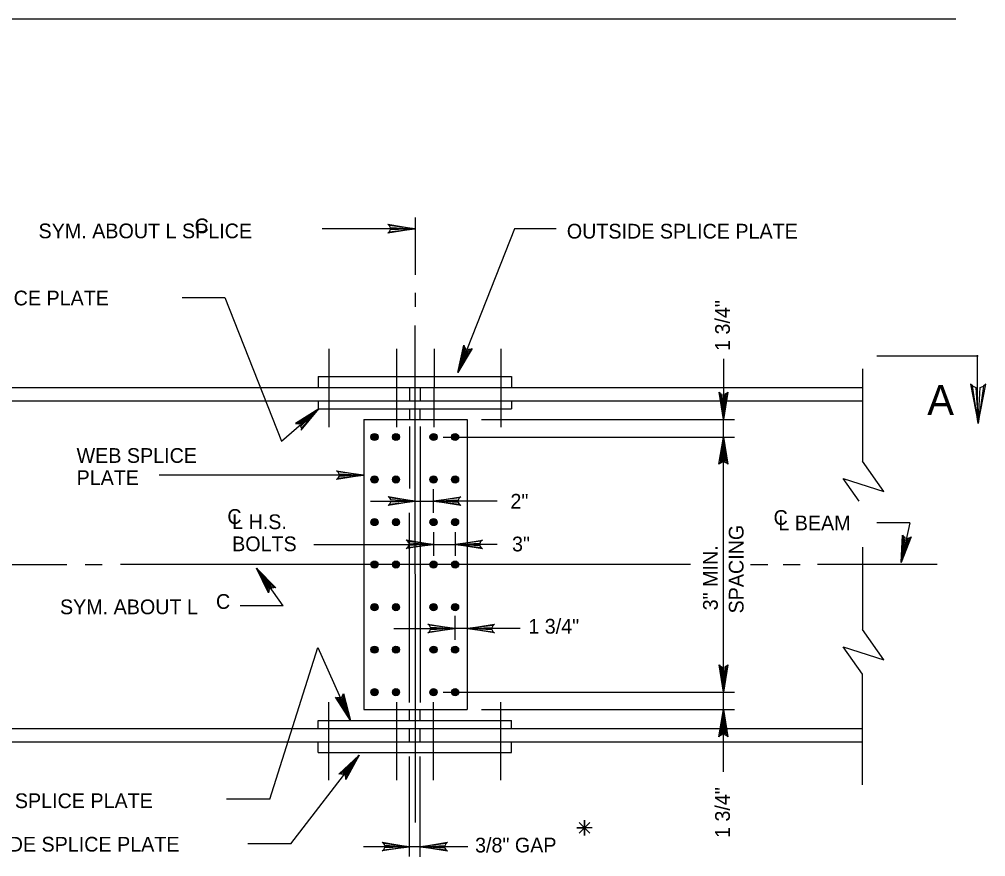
# Model space of a CAD drawing. Extents: x 638466 to 639375, y 297808 to 298996.
# Drawn here: x 638619.3 to 638831.8, y 298507.4 to 298691.6 of the extents above; entities that cross this region are included whole.
import ezdxf

# ---------------------------------------------------------------- set-up
doc = ezdxf.new("R2010")
doc.units = 0
for name, color, linetype in [('1', 7, 'Continuous'), ('2', 7, 'Continuous'), ('4', 7, 'Continuous')]:
    doc.layers.add(name, color=color, linetype=linetype)

msp = doc.modelspace()

# ---------------------------------------------------------------- linework, layer by layer
at = {"layer": '1'}
for points in [[(638700.6, 298646.27), (638700.81, 298645.85), (638706.32, 298645.55), (638700.6, 298646.27), (638700.3, 298646.52), (638706.32, 298645.55), (638700.81, 298645.28), (638700.61, 298644.86), (638706.32, 298645.55), (638700.3, 298644.59), (638700.61, 298644.86)], [(638718.49, 298619.02), (638718.03, 298618.97), (638715.72, 298613.96), (638718.49, 298619.02), (638718.83, 298619.2), (638715.72, 298613.96), (638717.49, 298619.18), (638717.18, 298619.52), (638715.72, 298613.96), (638717.04, 298619.91), (638717.18, 298619.52)], [(638828.91, 298610.97), (638829.62, 298610.66), (638830.15, 298602.73), (638828.91, 298610.97), (638828.47, 298611.39), (638830.15, 298602.73), (638830.61, 298610.65), (638831.32, 298610.95), (638830.15, 298602.73), (638831.8, 298611.39), (638831.32, 298610.95)], [(638774.83, 298609.29), (638774.42, 298609.08), (638774.11, 298603.57), (638774.83, 298609.29), (638775.08, 298609.58), (638774.11, 298603.57), (638773.84, 298609.07), (638773.43, 298609.27), (638774.11, 298603.57), (638773.16, 298609.58), (638773.43, 298609.27)], [(638681.3, 298601.65), (638681.19, 298602.1), (638685.16, 298605.93), (638681.3, 298601.65), (638681.24, 298601.27), (638685.16, 298605.93), (638680.82, 298602.54), (638680.4, 298602.72), (638685.16, 298605.93), (638679.98, 298602.73), (638680.4, 298602.72)], [(638773.4, 298594.02), (638773.81, 298594.23), (638774.11, 298599.74), (638773.4, 298594.02), (638773.14, 298593.73), (638774.11, 298599.74), (638774.38, 298594.24), (638774.8, 298594.04), (638774.11, 298599.74), (638775.07, 298593.73), (638774.8, 298594.04)], [(638689.3, 298592.05), (638689.51, 298591.64), (638695.02, 298591.33), (638689.3, 298592.05), (638689.01, 298592.3), (638695.02, 298591.33), (638689.51, 298591.06), (638689.31, 298590.65), (638695.02, 298591.33), (638689.01, 298590.38), (638689.31, 298590.65)], [(638700.66, 298586.38), (638700.87, 298585.96), (638706.38, 298585.66), (638700.66, 298586.38), (638700.37, 298586.63), (638706.38, 298585.66), (638700.88, 298585.39), (638700.68, 298584.97), (638706.38, 298585.66), (638700.37, 298584.7), (638700.68, 298584.97)], [(638716.1, 298584.94), (638715.88, 298585.35), (638710.37, 298585.66), (638716.1, 298584.94), (638716.39, 298584.69), (638710.37, 298585.66), (638715.88, 298585.93), (638716.08, 298586.34), (638710.37, 298585.66), (638716.39, 298586.61), (638716.08, 298586.34)], [(638704.65, 298576.85), (638704.87, 298576.43), (638710.37, 298576.13), (638704.65, 298576.85), (638704.36, 298577.1), (638710.37, 298576.13), (638704.87, 298575.86), (638704.67, 298575.45), (638710.37, 298576.13), (638704.36, 298575.18), (638704.67, 298575.45)], [(638720.82, 298575.41), (638720.61, 298575.82), (638715.1, 298576.13), (638720.82, 298575.41), (638721.11, 298575.16), (638715.1, 298576.13), (638720.6, 298576.4), (638720.8, 298576.81), (638715.1, 298576.13), (638721.11, 298577.08), (638720.8, 298576.81)], [(638815.1, 298577.54), (638814.65, 298577.42), (638813.19, 298572.1), (638815.1, 298577.54), (638815.41, 298577.77), (638813.19, 298572.1), (638814.09, 298577.54), (638813.73, 298577.82), (638813.19, 298572.1), (638813.53, 298578.18), (638813.73, 298577.82)], [(638674.13, 298565.82), (638674.34, 298566.24), (638671.4, 298570.91), (638674.13, 298565.82), (638674.09, 298565.44), (638671.4, 298570.91), (638674.81, 298566.58), (638675.26, 298566.65), (638671.4, 298570.91), (638675.66, 298566.55), (638675.26, 298566.65)], [(638709.38, 298558.32), (638709.59, 298557.9), (638715.1, 298557.6), (638709.38, 298558.32), (638709.09, 298558.57), (638715.1, 298557.6), (638709.59, 298557.33), (638709.39, 298556.92), (638715.1, 298557.6), (638709.09, 298556.65), (638709.39, 298556.92)], [(638723.46, 298556.88), (638723.25, 298557.29), (638717.74, 298557.6), (638723.46, 298556.88), (638723.75, 298556.63), (638717.74, 298557.6), (638723.25, 298557.87), (638723.45, 298558.28), (638717.74, 298557.6), (638723.75, 298558.55), (638723.45, 298558.28)], [(638774.83, 298549.33), (638774.42, 298549.12), (638774.11, 298543.61), (638774.83, 298549.33), (638775.08, 298549.62), (638774.11, 298543.61), (638773.84, 298549.11), (638773.43, 298549.32), (638774.11, 298543.61), (638773.16, 298549.62), (638773.43, 298549.32)], [(638690.42, 298542.94), (638690.13, 298542.58), (638692.09, 298537.42), (638690.42, 298542.94), (638690.53, 298543.31), (638692.09, 298537.42), (638689.6, 298542.34), (638689.15, 298542.36), (638692.09, 298537.42), (638688.77, 298542.53), (638689.15, 298542.36)], [(638773.4, 298534.07), (638773.81, 298534.28), (638774.11, 298539.79), (638773.4, 298534.07), (638773.14, 298533.77), (638774.11, 298539.79), (638774.38, 298534.28), (638774.8, 298534.08), (638774.11, 298539.79), (638775.07, 298533.77), (638774.8, 298534.08)], [(638689.95, 298525.68), (638690.41, 298525.6), (638694.01, 298529.78), (638689.95, 298525.68), (638689.57, 298525.6), (638694.01, 298529.78), (638690.87, 298525.25), (638691.07, 298524.84), (638694.01, 298529.78), (638691.1, 298524.43), (638691.07, 298524.84)], [(638699.34, 298510.35), (638699.55, 298509.93), (638705.06, 298509.63), (638699.34, 298510.35), (638699.04, 298510.6), (638705.06, 298509.63), (638699.55, 298509.36), (638699.35, 298508.95), (638705.06, 298509.63), (638699.04, 298508.68), (638699.35, 298508.95)], [(638713.14, 298508.91), (638712.93, 298509.33), (638707.42, 298509.63), (638713.14, 298508.91), (638713.43, 298508.66), (638707.42, 298509.63), (638712.92, 298509.9), (638713.12, 298510.31), (638707.42, 298509.63), (638713.43, 298510.59), (638713.12, 298510.31)]]:
    msp.add_lwpolyline(points, dxfattribs=at)
at = {"layer": '2'}
for p, q in [((638706.31, 298648.02), (638706.32, 298635.41)), ((638706.33, 298631.47), (638706.33, 298628.4)), ((638706.42, 298514.94), (638706.33, 298624.24)), ((638687.34, 298619.12), (638687.34, 298601.93)), ((638702.2, 298619.12), (638702.21, 298601.94)), ((638710.47, 298619.12), (638710.46, 298601.94)), ((638725.14, 298619.12), (638725.14, 298601.93)), ((638804.7, 298614.72), (638804.7, 298594.42)), ((638684.98, 298613.02), (638727.5, 298613.02)), ((638684.98, 298613.02), (638684.98, 298610.65)), ((638727.5, 298613.02), (638727.5, 298610.65)), ((638607.78, 298610.65), (638804.7, 298610.65)), ((638705.06, 298610.65), (638705.06, 298607.7)), ((638707.42, 298610.65), (638707.42, 298607.7)), ((638607.78, 298607.7), (638804.7, 298607.7)), ((638684.98, 298607.7), (638684.98, 298605.93)), ((638727.5, 298607.7), (638727.5, 298605.93)), ((638684.98, 298605.93), (638727.5, 298605.93)), ((638705.06, 298605.93), (638705.06, 298603.57)), ((638707.42, 298603.57), (638707.42, 298605.93)), ((638695.02, 298603.57), (638717.74, 298603.57)), ((638695.02, 298603.57), (638695.02, 298539.79)), ((638717.74, 298603.57), (638717.74, 298539.79)), ((638705.06, 298602.02), (638705.06, 298588.4)), ((638707.42, 298602.02), (638707.42, 298541.34)), ((638809.43, 298587.77), (638804.7, 298594.42)), ((638803.97, 298585.66), (638800.44, 298590.62)), ((638800.44, 298590.62), (638809.43, 298587.77)), ((638705.06, 298541.34), (638705.06, 298583.08)), ((638804.7, 298575.51), (638804.7, 298557.37)), ((638809.43, 298550.72), (638804.7, 298557.37)), ((638804.7, 298547.58), (638800.44, 298553.57)), ((638800.44, 298553.57), (638809.43, 298550.72)), ((638804.7, 298523.27), (638804.7, 298547.59)), ((638687.34, 298524.23), (638687.34, 298541.42)), ((638702.3, 298524.23), (638702.3, 298541.42)), ((638710.37, 298524.23), (638710.37, 298541.42)), ((638725.14, 298524.23), (638725.14, 298541.42)), ((638695.02, 298539.79), (638717.74, 298539.79)), ((638705.06, 298537.42), (638705.06, 298539.79)), ((638707.42, 298537.42), (638707.42, 298539.79)), ((638684.98, 298537.42), (638727.5, 298537.42)), ((638684.98, 298535.65), (638684.98, 298537.42)), ((638727.5, 298535.65), (638727.5, 298537.42)), ((638607.78, 298535.65), (638804.7, 298535.65)), ((638705.06, 298532.7), (638705.06, 298535.65)), ((638707.42, 298532.7), (638707.42, 298535.65)), ((638607.78, 298532.69), (638804.7, 298532.69)), ((638684.98, 298530.34), (638684.98, 298532.7)), ((638727.5, 298530.34), (638727.5, 298532.7)), ((638684.98, 298530.34), (638727.5, 298530.34))]:
    msp.add_line(p, q, dxfattribs=at)
for centre, radius in [((638697.38, 298599.74), 0.783), ((638697.38, 298599.74), 0.727), ((638697.38, 298599.74), 0.672), ((638702.11, 298599.74), 0.783), ((638702.11, 298599.74), 0.727), ((638702.11, 298599.74), 0.672), ((638710.37, 298599.74), 0.783), ((638710.37, 298599.74), 0.727), ((638710.37, 298599.74), 0.672), ((638715.1, 298599.74), 0.783), ((638715.1, 298599.74), 0.727), ((638715.1, 298599.74), 0.672), ((638697.38, 298599.74), 0.616), ((638697.38, 298599.74), 0.561), ((638697.38, 298599.74), 0.505), ((638697.38, 298599.74), 0.449), ((638697.38, 298599.74), 0.394), ((638697.38, 298599.74), 0.338), ((638697.38, 298599.74), 0.283), ((638697.38, 298599.74), 0.227), ((638697.38, 298599.74), 0.171), ((638697.38, 298599.74), 0.116), ((638697.38, 298599.74), 0.0601), ((638702.11, 298599.74), 0.616), ((638702.11, 298599.74), 0.561), ((638702.11, 298599.74), 0.505), ((638702.11, 298599.74), 0.449), ((638702.11, 298599.74), 0.394), ((638702.11, 298599.74), 0.338), ((638702.11, 298599.74), 0.283), ((638702.11, 298599.74), 0.227), ((638702.11, 298599.74), 0.171), ((638702.11, 298599.74), 0.116), ((638702.11, 298599.74), 0.0601), ((638710.37, 298599.74), 0.616), ((638710.37, 298599.74), 0.561), ((638710.37, 298599.74), 0.505), ((638710.37, 298599.74), 0.449), ((638710.37, 298599.74), 0.394), ((638710.37, 298599.74), 0.338), ((638710.37, 298599.74), 0.283), ((638710.37, 298599.74), 0.227), ((638710.37, 298599.74), 0.171), ((638710.37, 298599.74), 0.116), ((638710.37, 298599.74), 0.0601), ((638715.1, 298599.74), 0.616), ((638715.1, 298599.74), 0.561), ((638715.1, 298599.74), 0.505), ((638715.1, 298599.74), 0.449), ((638715.1, 298599.74), 0.394), ((638715.1, 298599.74), 0.338), ((638715.1, 298599.74), 0.283), ((638715.1, 298599.74), 0.227), ((638715.1, 298599.74), 0.171), ((638715.1, 298599.74), 0.116), ((638715.1, 298599.74), 0.0601), ((638697.38, 298590.39), 0.783), ((638697.38, 298590.39), 0.727), ((638697.38, 298590.39), 0.672), ((638697.38, 298590.39), 0.616), ((638697.38, 298590.39), 0.561), ((638697.38, 298590.39), 0.505), ((638697.38, 298590.39), 0.449), ((638697.38, 298590.39), 0.394), ((638697.38, 298590.39), 0.338), ((638697.38, 298590.39), 0.283), ((638697.38, 298590.39), 0.227), ((638697.38, 298590.39), 0.171), ((638697.38, 298590.39), 0.116), ((638697.38, 298590.39), 0.0601), ((638702.11, 298590.39), 0.783), ((638702.11, 298590.39), 0.727), ((638702.11, 298590.39), 0.672), ((638702.11, 298590.39), 0.616), ((638702.11, 298590.39), 0.561), ((638702.11, 298590.39), 0.505), ((638702.11, 298590.39), 0.449), ((638702.11, 298590.39), 0.394), ((638702.11, 298590.39), 0.338), ((638702.11, 298590.39), 0.283), ((638702.11, 298590.39), 0.227), ((638702.11, 298590.39), 0.171), ((638702.11, 298590.39), 0.116), ((638702.11, 298590.39), 0.0601), ((638710.37, 298590.39), 0.783), ((638710.37, 298590.39), 0.727), ((638710.37, 298590.39), 0.672), ((638710.37, 298590.39), 0.616), ((638710.37, 298590.39), 0.561), ((638710.37, 298590.39), 0.505), ((638710.37, 298590.39), 0.449), ((638710.37, 298590.39), 0.394), ((638710.37, 298590.39), 0.338), ((638710.37, 298590.39), 0.283), ((638710.37, 298590.39), 0.227), ((638710.37, 298590.39), 0.171), ((638710.37, 298590.39), 0.116), ((638710.37, 298590.39), 0.0601), ((638715.1, 298590.39), 0.783), ((638715.1, 298590.39), 0.727), ((638715.1, 298590.39), 0.672), ((638715.1, 298590.39), 0.616), ((638715.1, 298590.39), 0.561), ((638715.1, 298590.39), 0.505), ((638715.1, 298590.39), 0.449), ((638715.1, 298590.39), 0.394), ((638715.1, 298590.39), 0.338), ((638715.1, 298590.39), 0.283), ((638715.1, 298590.39), 0.227), ((638715.1, 298590.39), 0.171), ((638715.1, 298590.39), 0.116), ((638715.1, 298590.39), 0.0601), ((638697.38, 298581.03), 0.783), ((638697.38, 298581.03), 0.727), ((638697.38, 298581.03), 0.672), ((638697.38, 298581.03), 0.616), ((638697.38, 298581.03), 0.561), ((638697.38, 298581.03), 0.505), ((638697.38, 298581.03), 0.449), ((638697.38, 298581.03), 0.394), ((638697.38, 298581.03), 0.338), ((638697.38, 298581.03), 0.283), ((638697.38, 298581.03), 0.227), ((638702.11, 298581.03), 0.783), ((638702.11, 298581.03), 0.727), ((638702.11, 298581.03), 0.672), ((638702.11, 298581.03), 0.616), ((638702.11, 298581.03), 0.561), ((638702.11, 298581.03), 0.505), ((638702.11, 298581.03), 0.449), ((638702.11, 298581.03), 0.394), ((638702.11, 298581.03), 0.338), ((638702.11, 298581.03), 0.283), ((638702.11, 298581.03), 0.227), ((638710.37, 298581.03), 0.783), ((638710.37, 298581.03), 0.727), ((638710.37, 298581.03), 0.672), ((638710.37, 298581.03), 0.616), ((638710.37, 298581.03), 0.561), ((638710.37, 298581.03), 0.505), ((638710.37, 298581.03), 0.449), ((638710.37, 298581.03), 0.394), ((638710.37, 298581.03), 0.338), ((638710.37, 298581.03), 0.283), ((638710.37, 298581.03), 0.227), ((638715.1, 298581.03), 0.783), ((638715.1, 298581.03), 0.727), ((638715.1, 298581.03), 0.672), ((638715.1, 298581.03), 0.616), ((638715.1, 298581.03), 0.561), ((638715.1, 298581.03), 0.505), ((638715.1, 298581.03), 0.449), ((638715.1, 298581.03), 0.394), ((638715.1, 298581.03), 0.338), ((638715.1, 298581.03), 0.283), ((638715.1, 298581.03), 0.227), ((638697.38, 298581.03), 0.171), ((638697.38, 298581.03), 0.116), ((638697.38, 298581.03), 0.0601), ((638702.11, 298581.03), 0.171), ((638702.11, 298581.03), 0.116), ((638702.11, 298581.03), 0.0601), ((638710.37, 298581.03), 0.171), ((638710.37, 298581.03), 0.116), ((638710.37, 298581.03), 0.0601), ((638715.1, 298581.03), 0.171), ((638715.1, 298581.03), 0.116), ((638715.1, 298581.03), 0.0601), ((638697.38, 298571.68), 0.783), ((638697.38, 298571.68), 0.727), ((638697.38, 298571.68), 0.672), ((638697.38, 298571.68), 0.616), ((638697.38, 298571.68), 0.561), ((638697.38, 298571.68), 0.505), ((638697.38, 298571.68), 0.449), ((638697.38, 298571.68), 0.394), ((638697.38, 298571.68), 0.338), ((638697.38, 298571.68), 0.283), ((638697.38, 298571.68), 0.227), ((638697.38, 298571.68), 0.171), ((638697.38, 298571.68), 0.116), ((638697.38, 298571.68), 0.0601), ((638702.11, 298571.68), 0.783), ((638702.11, 298571.68), 0.727), ((638702.11, 298571.68), 0.672), ((638702.11, 298571.68), 0.616), ((638702.11, 298571.68), 0.561), ((638702.11, 298571.68), 0.505), ((638702.11, 298571.68), 0.449), ((638702.11, 298571.68), 0.394), ((638702.11, 298571.68), 0.338), ((638702.11, 298571.68), 0.283), ((638702.11, 298571.68), 0.227), ((638702.11, 298571.68), 0.171), ((638702.11, 298571.68), 0.116), ((638702.11, 298571.68), 0.0601), ((638710.37, 298571.68), 0.783), ((638710.37, 298571.68), 0.727), ((638710.37, 298571.68), 0.672), ((638710.37, 298571.68), 0.616), ((638710.37, 298571.68), 0.561), ((638710.37, 298571.68), 0.505), ((638710.37, 298571.68), 0.449), ((638710.37, 298571.68), 0.394), ((638710.37, 298571.68), 0.338), ((638710.37, 298571.68), 0.283), ((638710.37, 298571.68), 0.227), ((638710.37, 298571.68), 0.171), ((638710.37, 298571.68), 0.116), ((638710.37, 298571.68), 0.0601), ((638715.1, 298571.68), 0.783), ((638715.1, 298571.68), 0.727), ((638715.1, 298571.68), 0.672), ((638715.1, 298571.68), 0.616), ((638715.1, 298571.68), 0.561), ((638715.1, 298571.68), 0.505), ((638715.1, 298571.68), 0.449), ((638715.1, 298571.68), 0.394), ((638715.1, 298571.68), 0.338), ((638715.1, 298571.68), 0.283), ((638715.1, 298571.68), 0.227), ((638715.1, 298571.68), 0.171), ((638715.1, 298571.68), 0.116), ((638715.1, 298571.68), 0.0601), ((638697.38, 298562.32), 0.783), ((638697.38, 298562.32), 0.727), ((638697.38, 298562.32), 0.672), ((638697.38, 298562.32), 0.616), ((638697.38, 298562.32), 0.561), ((638697.38, 298562.32), 0.505), ((638697.38, 298562.32), 0.449), ((638697.38, 298562.32), 0.394), ((638697.38, 298562.32), 0.338), ((638697.38, 298562.32), 0.283), ((638697.38, 298562.32), 0.227), ((638697.38, 298562.32), 0.171), ((638697.38, 298562.32), 0.116), ((638697.38, 298562.32), 0.0601), ((638702.11, 298562.32), 0.783), ((638702.11, 298562.32), 0.727), ((638702.11, 298562.32), 0.672), ((638702.11, 298562.32), 0.616), ((638702.11, 298562.32), 0.561), ((638702.11, 298562.32), 0.505), ((638702.11, 298562.32), 0.449), ((638702.11, 298562.32), 0.394), ((638702.11, 298562.32), 0.338), ((638702.11, 298562.32), 0.283), ((638702.11, 298562.32), 0.227), ((638702.11, 298562.32), 0.171), ((638702.11, 298562.32), 0.116), ((638702.11, 298562.32), 0.0601), ((638710.37, 298562.32), 0.783), ((638710.37, 298562.32), 0.727), ((638710.37, 298562.32), 0.672), ((638710.37, 298562.32), 0.616), ((638710.37, 298562.32), 0.561), ((638710.37, 298562.32), 0.505), ((638710.37, 298562.32), 0.449), ((638710.37, 298562.32), 0.394), ((638710.37, 298562.32), 0.338), ((638710.37, 298562.32), 0.283), ((638710.37, 298562.32), 0.227), ((638710.37, 298562.32), 0.171), ((638710.37, 298562.32), 0.116), ((638710.37, 298562.32), 0.0601), ((638715.1, 298562.32), 0.783), ((638715.1, 298562.32), 0.727), ((638715.1, 298562.32), 0.672), ((638715.1, 298562.32), 0.616), ((638715.1, 298562.32), 0.561), ((638715.1, 298562.32), 0.505), ((638715.1, 298562.32), 0.449), ((638715.1, 298562.32), 0.394), ((638715.1, 298562.32), 0.338), ((638715.1, 298562.32), 0.283), ((638715.1, 298562.32), 0.227), ((638715.1, 298562.32), 0.171), ((638715.1, 298562.32), 0.116), ((638715.1, 298562.32), 0.0601), ((638697.38, 298552.97), 0.783), ((638697.38, 298552.97), 0.727), ((638697.38, 298552.97), 0.672), ((638702.11, 298552.97), 0.783), ((638702.11, 298552.97), 0.727), ((638702.11, 298552.97), 0.672), ((638710.37, 298552.97), 0.783), ((638710.37, 298552.97), 0.727), ((638710.37, 298552.97), 0.672), ((638715.1, 298552.97), 0.783), ((638715.1, 298552.97), 0.727), ((638715.1, 298552.97), 0.672), ((638697.38, 298552.97), 0.616), ((638697.38, 298552.97), 0.561), ((638697.38, 298552.97), 0.505), ((638697.38, 298552.97), 0.449), ((638697.38, 298552.97), 0.394), ((638697.38, 298552.97), 0.338), ((638697.38, 298552.97), 0.283), ((638697.38, 298552.97), 0.227), ((638697.38, 298552.97), 0.171), ((638697.38, 298552.97), 0.116), ((638697.38, 298552.97), 0.0601), ((638702.11, 298552.97), 0.616), ((638702.11, 298552.97), 0.561), ((638702.11, 298552.97), 0.505), ((638702.11, 298552.97), 0.449), ((638702.11, 298552.97), 0.394), ((638702.11, 298552.97), 0.338), ((638702.11, 298552.97), 0.283), ((638702.11, 298552.97), 0.227), ((638702.11, 298552.97), 0.171), ((638702.11, 298552.97), 0.116), ((638702.11, 298552.97), 0.0601), ((638710.37, 298552.97), 0.616), ((638710.37, 298552.97), 0.561), ((638710.37, 298552.97), 0.505), ((638710.37, 298552.97), 0.449), ((638710.37, 298552.97), 0.394), ((638710.37, 298552.97), 0.338), ((638710.37, 298552.97), 0.283), ((638710.37, 298552.97), 0.227), ((638710.37, 298552.97), 0.171), ((638710.37, 298552.97), 0.116), ((638710.37, 298552.97), 0.0601), ((638715.1, 298552.97), 0.616), ((638715.1, 298552.97), 0.561), ((638715.1, 298552.97), 0.505), ((638715.1, 298552.97), 0.449), ((638715.1, 298552.97), 0.394), ((638715.1, 298552.97), 0.338), ((638715.1, 298552.97), 0.283), ((638715.1, 298552.97), 0.227), ((638715.1, 298552.97), 0.171), ((638715.1, 298552.97), 0.116), ((638715.1, 298552.97), 0.0601), ((638697.38, 298543.61), 0.783), ((638697.38, 298543.61), 0.727), ((638697.38, 298543.61), 0.672), ((638697.38, 298543.61), 0.616), ((638697.38, 298543.61), 0.561), ((638697.38, 298543.61), 0.505), ((638697.38, 298543.61), 0.449), ((638697.38, 298543.61), 0.394), ((638697.38, 298543.61), 0.338), ((638697.38, 298543.61), 0.283), ((638697.38, 298543.61), 0.227), ((638697.38, 298543.61), 0.171), ((638697.38, 298543.61), 0.116), ((638697.38, 298543.61), 0.0601), ((638702.11, 298543.61), 0.783), ((638702.11, 298543.61), 0.727), ((638702.11, 298543.61), 0.672), ((638702.11, 298543.61), 0.616), ((638702.11, 298543.61), 0.561), ((638702.11, 298543.61), 0.505), ((638702.11, 298543.61), 0.449), ((638702.11, 298543.61), 0.394), ((638702.11, 298543.61), 0.338), ((638702.11, 298543.61), 0.283), ((638702.11, 298543.61), 0.227), ((638702.11, 298543.61), 0.171), ((638702.11, 298543.61), 0.116), ((638702.11, 298543.61), 0.0601), ((638710.37, 298543.61), 0.783), ((638710.37, 298543.61), 0.727), ((638710.37, 298543.61), 0.672), ((638710.37, 298543.61), 0.616), ((638710.37, 298543.61), 0.561), ((638710.37, 298543.61), 0.505), ((638710.37, 298543.61), 0.449), ((638710.37, 298543.61), 0.394), ((638710.37, 298543.61), 0.338), ((638710.37, 298543.61), 0.283), ((638710.37, 298543.61), 0.227), ((638710.37, 298543.61), 0.171), ((638710.37, 298543.61), 0.116), ((638710.37, 298543.61), 0.0601), ((638715.1, 298543.61), 0.783), ((638715.1, 298543.61), 0.727), ((638715.1, 298543.61), 0.672), ((638715.1, 298543.61), 0.616), ((638715.1, 298543.61), 0.561), ((638715.1, 298543.61), 0.505), ((638715.1, 298543.61), 0.449), ((638715.1, 298543.61), 0.394), ((638715.1, 298543.61), 0.338), ((638715.1, 298543.61), 0.283), ((638715.1, 298543.61), 0.227), ((638715.1, 298543.61), 0.171), ((638715.1, 298543.61), 0.116), ((638715.1, 298543.61), 0.0601)]:
    msp.add_circle(centre, radius, dxfattribs=at)
at = {"layer": '4'}
for p, q in [((638825.25, 298691.61), (638605.94, 298691.61)), ((638706.32, 298645.55), (638685.88, 298645.55)), ((638728.17, 298645.55), (638715.72, 298613.96)), ((638737.33, 298645.55), (638728.17, 298645.55)), ((638655.08, 298630.39), (638664.45, 298630.39)), ((638664.45, 298630.39), (638676.9, 298598.8)), ((638807.89, 298617.57), (638830.15, 298617.57)), ((638830, 298605.01), (638830, 298617.72)), ((638774.11, 298616.91), (638774.11, 298603.57)), ((638676.9, 298598.8), (638685.16, 298605.93)), ((638720.89, 298603.57), (638776.56, 298603.57)), ((638774.11, 298539.79), (638774.11, 298603.57)), ((638712.5, 298599.74), (638776.56, 298599.74)), ((638695.02, 298591.33), (638650.04, 298591.33)), ((638710.37, 298583.07), (638710.37, 298588.3)), ((638696.51, 298585.66), (638706.38, 298585.66)), ((638706.36, 298585.66), (638710.37, 298585.66)), ((638724.39, 298585.66), (638710.37, 298585.66)), ((638815.09, 298580.86), (638807.83, 298580.86)), ((638815.09, 298580.86), (638813.19, 298572.1)), ((638710.37, 298578.8), (638710.37, 298573.57)), ((638715.1, 298578.8), (638715.1, 298573.57)), ((638684.01, 298576.13), (638710.37, 298576.13)), ((638710.37, 298576.13), (638715.1, 298576.13)), ((638724.39, 298576.13), (638715.1, 298576.13)), ((638595.76, 298571.68), (638629.71, 298571.68)), ((638633.72, 298571.68), (638637.52, 298571.68)), ((638766.87, 298571.68), (638641.52, 298571.68)), ((638677.31, 298562.58), (638671.4, 298570.91)), ((638780.06, 298571.68), (638783.86, 298571.68)), ((638787.23, 298571.68), (638791.03, 298571.68)), ((638821.1, 298571.68), (638794.83, 298571.68)), ((638677.31, 298562.58), (638667.81, 298562.58)), ((638715.1, 298555.14), (638715.1, 298560.37)), ((638701.62, 298557.6), (638715.1, 298557.6)), ((638729.45, 298557.6), (638715.1, 298557.6)), ((638674.36, 298520.1), (638684.94, 298553.47)), ((638684.94, 298553.47), (638692.09, 298537.42)), ((638712.5, 298543.61), (638776.56, 298543.61)), ((638720.89, 298539.79), (638776.56, 298539.79)), ((638774.11, 298526.07), (638774.11, 298539.79)), ((638679, 298510.28), (638694.01, 298529.78)), ((638705.06, 298507.48), (638705.06, 298529.43)), ((638707.42, 298507.43), (638707.42, 298529.43)), ((638674.36, 298520.1), (638664.86, 298520.1)), ((638743.55, 298513.77), (638743.55, 298513.77)), ((638679, 298510.28), (638669.5, 298510.28)), ((638717.88, 298509.63), (638694.97, 298509.63))]:
    msp.add_line(p, q, dxfattribs=at)
msp.add_lwpolyline([(638745.24, 298513.77), (638741.87, 298513.77), (638743.55, 298513.77), (638743.55, 298512.08), (638743.55, 298515.45), (638743.55, 298513.77), (638744.75, 298514.96), (638742.36, 298512.57), (638743.55, 298513.77), (638744.75, 298512.57), (638742.36, 298514.96)], dxfattribs=at)

# ---------------------------------------------------------------- texts
for s, height, p in [('C', 3.24, (638657.81, 298644.56)), ('SYM. ABOUT L SPLICE', 3.2401, (638623.5, 298643.45)), ('OUTSIDE SPLICE PLATE', 3.2401, (638739.68, 298643.39)), ('INSIDE SPLICE PLATE', 3.2401, (638592.98, 298628.69)), ('A', 6.61, (638818.94, 298604.56)), ('WEB SPLICE', 3.24, (638631.86, 298594.05)), ('PLATE', 3.24, (638631.86, 298589.19)), ('2"', 3.24, (638727.28, 298583.99)), ('C', 3.24, (638665.02, 298580.63)), ('C', 3.24, (638785.15, 298580.42)), ('L H.S.', 3.24, (638666.07, 298579.48)), ('L BEAM', 3.24, (638786.2, 298579.22)), ('BOLTS', 3.24, (638666.07, 298574.62)), ('3"', 3.24, (638727.63, 298574.58)), ('C', 3.24, (638662.52, 298561.94)), ('SYM. ABOUT L', 3.2401, (638628.21, 298560.76)), ('1 3/4"', 3.24, (638731.22, 298556.49)), ('INSIDE SPLICE PLATE', 3.2401, (638602.64, 298518.11)), ('OUTSIDE SPLICE PLATE', 3.2401, (638603.69, 298508.55)), ('3/8" GAP', 3.24, (638719.5, 298508.36))]:
    msp.add_text(s, height=height, dxfattribs=at).set_placement(p)
for s, p in [('1 3/4"', (638775.54, 298618.67)), ('SPACING', (638778.55, 298560.93)), ('3" MIN.', (638772.88, 298561.61)), ('1 3/4"', (638775.54, 298511.54))]:
    msp.add_text(s, height=3.24, rotation=90, dxfattribs=at).set_placement(p)

doc.saveas('drawing.dxf')
